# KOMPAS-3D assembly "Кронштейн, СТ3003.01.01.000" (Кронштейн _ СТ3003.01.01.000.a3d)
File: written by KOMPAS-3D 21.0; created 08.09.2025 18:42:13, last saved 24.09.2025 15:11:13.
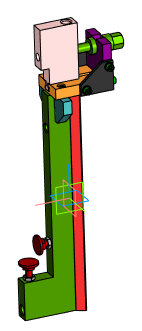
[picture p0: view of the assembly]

Document properties: Полное имя файла: C:\Users\1\Yandex.Disk\Документы\Новая папка\Стапель №2\Стапель _ СТ3003.00.00.000\Опора _ СТ3003.01.00.000\3D\Кронштейн _ СТ3003.01.01.000\Кронштейн _ СТ3003.01.01.000.a3d

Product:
- Part/product: Кронштейн  | designation СТ3003.01.01.000
    Масса: 9.381703
    Форматы листов документа: A2
  - Component [standard]: Гайка шестигранная низкая ГОСТ ISO 4035-М12-05-A2P  | qty 2  | pos. 13  | Материал: Сталь (density 1000 kg/m3); Масса: 0.001154; Раздел спецификации: Стандартные изделия; Рассекать на разрезах: no; additional columns: M12 - 05 - A2P
  - Component [detail]: Опора  | designation СТ3003.01.01.004  | qty 2  | pos. 5  | Материал: Круг$d35 ГОСТ 2590-2006;Ст3сп ГОСТ 535-2005$ (density 7850 kg/m3); Масса: 0.078797; Форматы листов документа: A4; source file: ..\..\2D\Кронштейн _ СТ3003.01.01.000\Опора _ СТ3003.01.01.004.cdw, Опора _ СТ3003.01.01.004.m3d
  - Component [standard]: Винт М8-6gx25.56.019 ГОСТ 11738-84  | qty 8  | pos. 11  | Материал: Сталь 30 ГОСТ 1050-2013 (density 1000 kg/m3); Масса: 0.01513; Раздел спецификации: Стандартные изделия; Рассекать на разрезах: no
  - Component [standard]: Шайба A.8.01.10.019 ГОСТ 11371-78  | qty 6  | pos. 12  | Масса: 0.001828; Раздел спецификации: Стандартные изделия; Рассекать на разрезах: no
  - Component [detail]: Косынка  | designation СТ3003.01.01.002  | qty 2  | pos. 3  | Материал: Лист$dБ-ПН-НО-6 ГОСТ 19903-2015;Ст3сп ГОСТ 14637-89$ (density 7850 kg/m3); Масса: 0.116828; Форматы листов документа: A4; source file: ..\..\2D\Кронштейн _ СТ3003.01.01.000\Косынка _ СТ3003.01.01.002.cdw, Косынка _ СТ3003.01.01.002.m3d
  - Component [detail]: Пластина  | designation СТ3003.01.01.006  | pos. 7  | Материал: Лист$dБ-ПН-НО-16 ГОСТ 19903-2015;Ст3сп ГОСТ 14637-89$ (density 7850 kg/m3); Масса: 0.669577; Форматы листов документа: A4; source file: Пластина _ СТ3003.01.01.006.m3d
  - Component [detail]: Направляющая  | designation СТ3003.01.01.003  | pos. 4  | Материал: Сталь 45  ГОСТ 1050-2013 (density 7810 kg/m3); Масса: 0.806848; Форматы листов документа: A3; source file: Направляющая _ СТ3003.01.01.003.m3d
  - Component [detail]: Планка  | designation СТ3003.01.01.005  | pos. 6  | Материал: Сталь 45  ГОСТ 1050-2013 (density 7810 kg/m3); Масса: 1.670176; Форматы листов документа: A3; source file: ..\..\2D\Кронштейн _ СТ3003.01.01.000\Планка _ СТ3003.01.01.005.cdw, Планка _ СТ3003.01.01.005.m3d
  - Component [assembly]: Основание  | designation СТ3003.01.01.100  | pos. 1  | Масса: 4.086618; Форматы листов документа: A3; source file: ..\..\2D\Кронштейн _ СТ3003.01.01.000\Основание _ СТ3003.01.01.100\Основание _ СТ3003.01.01.100.cdw, Основание _ СТ3003.01.01.100\Основание _ СТ3003.01.01.100.a3d
  - Component [detail]: Упор  | designation СТ3003.01.01.007  | pos. 8  | Материал: Сталь 45  ГОСТ 1050-2013 (density 7810 kg/m3); Масса: 1.271359; Форматы листов документа: A3; source file: Упор _ СТ.3003.01.01.007.m3d
  - Component [detail]: Винт  | designation СТ3003.01.01.001  | pos. 2  | Материал: Круг$d30 ГОСТ 2590-2006;Ст3сп ГОСТ 535-2005$ (density 7850 kg/m3); Масса: 0.311599; Форматы листов документа: A4; additional columns: 110; source file: ..\..\2D\Кронштейн _ СТ3003.01.01.000\Винт _ СТ3003.01.01.001.cdw, Винт _ СТ3003.01.01.001.m3d
  - Component [standard]: Винт М6-6gx20.56.019 ГОСТ 11738-84  | qty 6  | pos. 10  | Материал: Сталь 30 ГОСТ 1050-2013 (density 1000 kg/m3); Масса: 0.00666; Раздел спецификации: Стандартные изделия; Рассекать на разрезах: no

Referenced files in C:\Users\1\Yandex.Disk\Документы\Новая папка\Стапель №2\Стапель _ СТ3003.00.00.000\Опора _ СТ3003.01.00.000\3D\Кронштейн _ СТ3003.01.01.000\: Косынка _ СТ3003.01.01.002.m3d, Планка _ СТ3003.01.01.005.m3d, Направляющая _ СТ3003.01.01.003.m3d, Винт _ СТ3003.01.01.001.m3d, Пластина _ СТ3003.01.01.006.m3d, Упор _ СТ.3003.01.01.007.m3d, Опора _ СТ3003.01.01.004.m3d
Referenced files in C:\Users\1\Yandex.Disk\Документы\Новая папка\Стапель №2\Стапель _ СТ3003.00.00.000\Опора _ СТ3003.01.00.000\2D\Кронштейн _ СТ3003.01.01.000\: Косынка _ СТ3003.01.01.002.cdw, Планка _ СТ3003.01.01.005.cdw, Винт _ СТ3003.01.01.001.cdw, Опора _ СТ3003.01.01.004.cdw
Referenced files in C:\Users\1\Yandex.Disk\Документы\Новая папка\Стапель №2\Стапель _ СТ3003.00.00.000\Опора _ СТ3003.01.00.000\3D\Кронштейн _ СТ3003.01.01.000\Основание _ СТ3003.01.01.100\: Основание _ СТ3003.01.01.100.a3d
Referenced files in C:\Users\1\Yandex.Disk\Документы\Новая папка\Стапель №2\Стапель _ СТ3003.00.00.000\Опора _ СТ3003.01.00.000\2D\Кронштейн _ СТ3003.01.01.000\Основание _ СТ3003.01.01.100\: Основание _ СТ3003.01.01.100.cdw
Referenced files in C:\Program Files\ASCON\KOMPAS-3D v21\Libs\PartLib\DATA\VAULT\Methods\Kompas\3D\: PLib_Screw_GOST_11738_1500.m3d, PLib_Washer_1_712.m3d
Referenced files in C:\Program Files\ASCON\KOMPAS-3D v21\Libs\PARTLib\DATA\vault\Methods\Kompas\3D\: PLib_Nut_ISO_1100.m3d, PLib_Screw_GOST_11738_1500.m3d
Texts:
  СТ3003.01.01.002
  СТ3003.01.01.005
  СТ3003.01.01.003
  СТ3003.01.01.001
  СТ3003.01.01.006
  СТ3003.01.01.007
  СТ3003.01.01.100
  Крепежное изделие ГОСТ
  СТ3003.01.01.004
  Гайка шестигранная низкая
  СТ3003.01.01.000
  СТ3003.01.01.100 Основание
  СТ3003.01.01.005 Планка
  СТ3003.01.01.003 Направляющая
  СТ3003.01.01.006 Пластина
  СТ3003.01.01.002 Косынка (1)
  СТ3003.01.01.002 Косынка (2)
  СТ3003.01.01.007 Упор
  СТ3003.01.01.001 Винт
  Винт М8-6gx25.56.019 ГОСТ 11738-84 (1)
  Винт М8-6gx25.56.019 ГОСТ 11738-84 (2)
  Шайба A.8.01.10.019 ГОСТ 11371-78 (1)
  Шайба A.8.01.10.019 ГОСТ 11371-78 (2)
  Шайба A.8.01.10.019 ГОСТ 11371-78 (3)
  Шайба A.8.01.10.019 ГОСТ 11371-78 (4)
  Винт М8-6gx25.56.019 ГОСТ 11738-84 (3)
  Винт М8-6gx25.56.019 ГОСТ 11738-84 (4)
  Винт М8-6gx25.56.019 ГОСТ 11738-84 (5)
  Винт М8-6gx25.56.019 ГОСТ 11738-84 (6)
  Винт М6-6gx20.56.019 ГОСТ 11738-84 (1)
  Винт М6-6gx20.56.019 ГОСТ 11738-84 (2)
  Винт М6-6gx20.56.019 ГОСТ 11738-84 (3)
  Винт М6-6gx20.56.019 ГОСТ 11738-84 (4)
  Винт М6-6gx20.56.019 ГОСТ 11738-84 (5)
  Винт М6-6gx20.56.019 ГОСТ 11738-84 (6)
  Шайба A.8.01.10.019 ГОСТ 11371-78 (5)
  Шайба A.8.01.10.019 ГОСТ 11371-78 (6)
  Винт М8-6gx25.56.019 ГОСТ 11738-84 (7)
  Винт М8-6gx25.56.019 ГОСТ 11738-84 (8)
  СТ3003.01.01.004 Опора (1)
  СТ3003.01.01.004 Опора (2)
  bcut1
  hole1
  hcut1
  r1pt
  hole2
  cut1
  cut2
